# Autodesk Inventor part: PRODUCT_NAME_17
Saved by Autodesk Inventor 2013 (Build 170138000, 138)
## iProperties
Created: 2012-12
Part Number: PRODUCT_NAME_17
Material: Générique
Document SubType Name: Modeling
Designer: jost thierry
Density: 1 g/cm^3
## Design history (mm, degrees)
node "PRODUCT_NAME_171"
node "PRODUCT_NAME_17"
node "Base1"
